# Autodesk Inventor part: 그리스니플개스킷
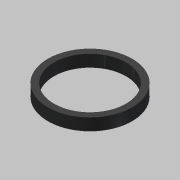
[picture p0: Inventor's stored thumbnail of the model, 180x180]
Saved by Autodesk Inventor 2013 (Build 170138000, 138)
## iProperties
Created: 2019-05
Part Number: 그리스니플개스킷
Material: 고무
Document SubType Name: Modeling
Designer: mduedu
Density: 1 g/cm^3
Author: mduedu
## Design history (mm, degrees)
sketch "스케치1"
  geometry: C1 r 3 at (0, 0); C2 r 3.5 at (0, 0); 1 further point
  constraints: 2 centre point, 2 coincident
  dimensions: "d0" = 6 diameter of C1; "d1" = 7 diameter of C2
extrude "돌출1" new body sketch "스케치1" distance "d2" = 1; taper "d3" = 0 deg
node "솔리드1"
